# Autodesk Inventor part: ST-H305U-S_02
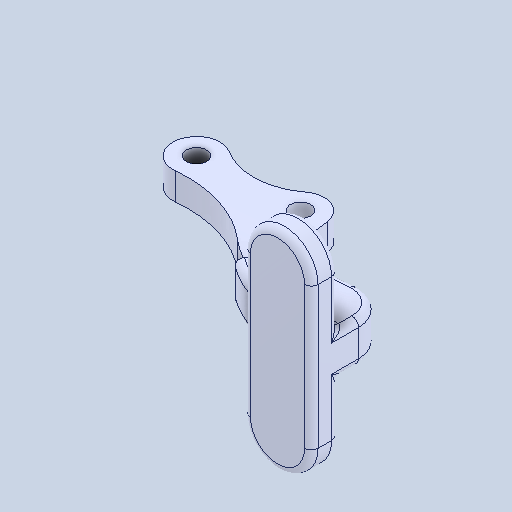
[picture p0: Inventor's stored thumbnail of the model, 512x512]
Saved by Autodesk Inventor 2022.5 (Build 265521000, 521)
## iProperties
Created: 2024-07
Part Number: ST-H305U-S_02
Material: 一般
Document SubType Name: Modeling
Designer: ImaoCorp
Density: 1 g/cm^3
Appearance: 既定
Author: ImaoCorp
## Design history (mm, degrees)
feature "ST-H305U-S_02"
node "ソリッド1"
